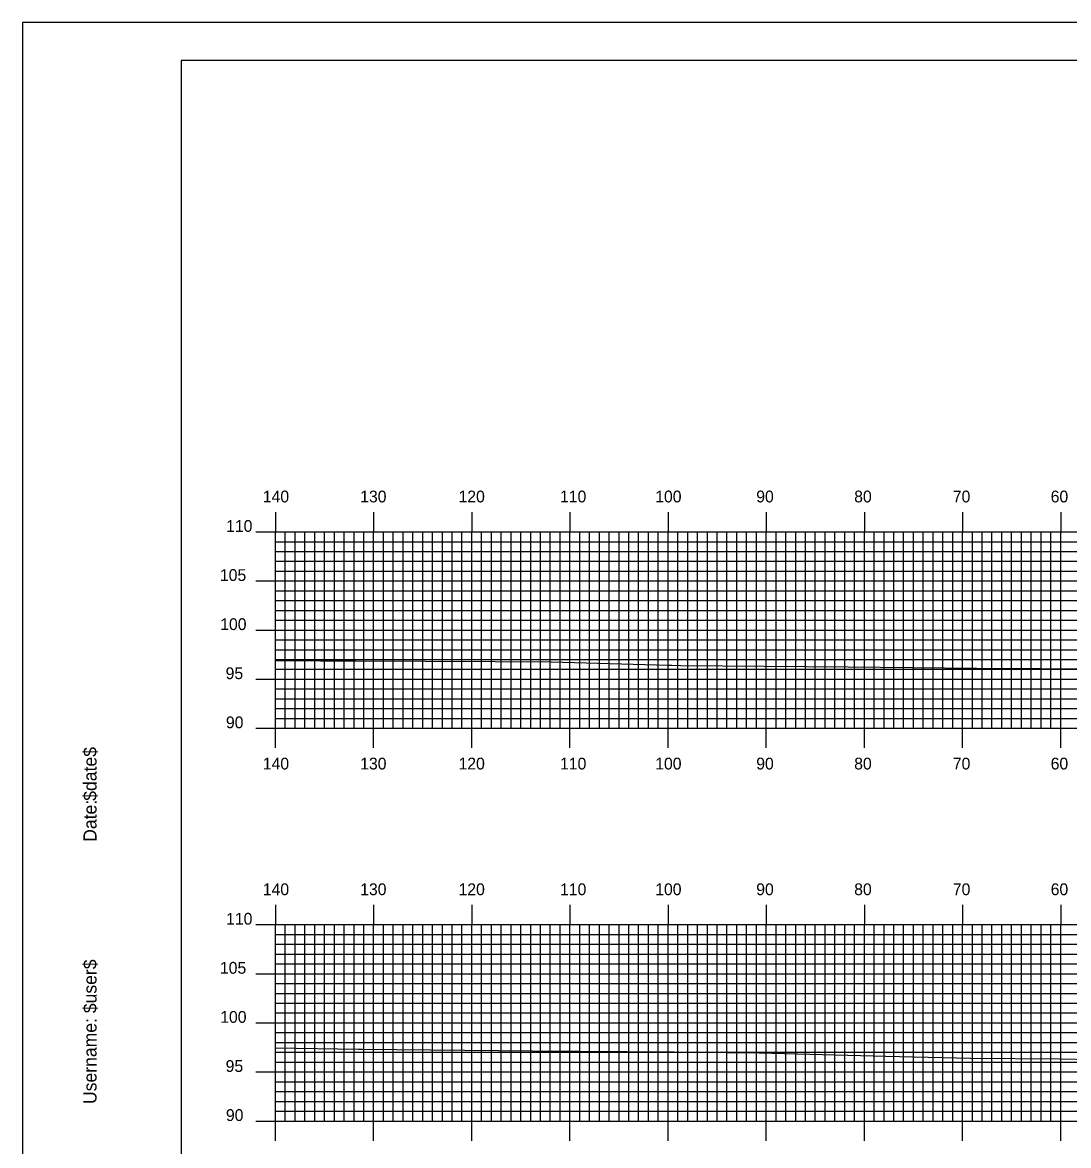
# Model space of a CAD drawing. Extents: x 1764546 to 1764889, y 442591 to 442811.
# Drawn here: x 1764545.6 to 1764652.1, y 442696.2 to 442810.5 of the extents above; entities that cross this region are included whole.
import ezdxf

# ---------------------------------------------------------------- set-up
doc = ezdxf.new("R2010")
doc.units = 0
for name, color, linetype in [('BORDER', 7, 'Continuous'), ('H_V ANNOTATION', 7, 'Continuous'), ('MAJOR', 7, 'Continuous'), ('MINOR', 7, 'Continuous'), ('PLOT BOUNDARY', 7, 'Continuous'), ('S_Roadway_Centerline', 7, 'Continuous')]:
    doc.layers.add(name, color=color, linetype=linetype)

msp = doc.modelspace()

# ---------------------------------------------------------------- linework, layer by layer
at = {"layer": 'BORDER'}
msp.add_lwpolyline([(1764561.74, 442596.67), (1764881.74, 442596.67), (1764881.74, 442806.67), (1764561.74, 442806.67)], close=True, dxfattribs=at)
at = {"layer": 'MAJOR'}
for p, q in [((1764571.34, 442760.67), (1764571.34, 442758.67)), ((1764581.34, 442760.67), (1764581.34, 442758.67)), ((1764591.34, 442760.67), (1764591.34, 442758.67)), ((1764601.34, 442760.67), (1764601.34, 442758.67)), ((1764611.34, 442760.67), (1764611.34, 442758.67)), ((1764621.34, 442760.67), (1764621.34, 442758.67)), ((1764631.34, 442760.67), (1764631.34, 442758.67)), ((1764641.34, 442760.67), (1764641.34, 442758.67)), ((1764651.34, 442760.67), (1764651.34, 442758.67)), ((1764569.34, 442758.67), (1764571.34, 442758.67)), ((1764571.34, 442758.67), (1764851.34, 442758.67)), ((1764571.34, 442738.67), (1764571.34, 442758.67)), ((1764571.34, 442738.67), (1764571.34, 442758.67)), ((1764571.34, 442758.67), (1764851.34, 442758.67)), ((1764581.34, 442738.67), (1764581.34, 442758.67)), ((1764591.34, 442738.67), (1764591.34, 442758.67)), ((1764601.34, 442738.67), (1764601.34, 442758.67)), ((1764611.34, 442738.67), (1764611.34, 442758.67)), ((1764621.34, 442738.67), (1764621.34, 442758.67)), ((1764631.34, 442738.67), (1764631.34, 442758.67)), ((1764641.34, 442738.67), (1764641.34, 442758.67)), ((1764651.34, 442738.67), (1764651.34, 442758.67)), ((1764569.34, 442753.67), (1764571.34, 442753.67)), ((1764571.34, 442753.67), (1764851.34, 442753.67)), ((1764569.34, 442748.67), (1764571.34, 442748.67)), ((1764571.34, 442748.67), (1764851.34, 442748.67)), ((1764569.34, 442743.67), (1764571.34, 442743.67)), ((1764571.34, 442743.67), (1764851.34, 442743.67)), ((1764569.34, 442738.67), (1764571.34, 442738.67)), ((1764571.34, 442738.67), (1764851.34, 442738.67)), ((1764571.34, 442738.67), (1764851.34, 442738.67)), ((1764571.34, 442736.66), (1764571.34, 442738.67)), ((1764581.34, 442736.66), (1764581.34, 442738.67)), ((1764591.34, 442736.66), (1764591.34, 442738.67)), ((1764601.34, 442736.66), (1764601.34, 442738.67)), ((1764611.34, 442736.66), (1764611.34, 442738.67)), ((1764621.34, 442736.66), (1764621.34, 442738.67)), ((1764631.34, 442736.66), (1764631.34, 442738.67)), ((1764641.34, 442736.66), (1764641.34, 442738.67)), ((1764651.34, 442736.66), (1764651.34, 442738.67)), ((1764571.34, 442720.67), (1764571.34, 442718.67)), ((1764581.34, 442720.67), (1764581.34, 442718.67)), ((1764591.34, 442720.67), (1764591.34, 442718.67)), ((1764601.34, 442720.67), (1764601.34, 442718.67)), ((1764611.34, 442720.67), (1764611.34, 442718.67)), ((1764621.34, 442720.67), (1764621.34, 442718.67)), ((1764631.34, 442720.67), (1764631.34, 442718.67)), ((1764641.34, 442720.67), (1764641.34, 442718.67)), ((1764651.34, 442720.67), (1764651.34, 442718.67)), ((1764569.34, 442718.67), (1764571.34, 442718.67)), ((1764571.34, 442718.67), (1764851.34, 442718.67)), ((1764571.34, 442698.67), (1764571.34, 442718.67)), ((1764571.34, 442698.67), (1764571.34, 442718.67)), ((1764571.34, 442718.67), (1764851.34, 442718.67)), ((1764581.34, 442698.67), (1764581.34, 442718.67)), ((1764591.34, 442698.67), (1764591.34, 442718.67)), ((1764601.34, 442698.67), (1764601.34, 442718.67)), ((1764611.34, 442698.67), (1764611.34, 442718.67)), ((1764621.34, 442698.67), (1764621.34, 442718.67)), ((1764631.34, 442698.67), (1764631.34, 442718.67)), ((1764641.34, 442698.67), (1764641.34, 442718.67)), ((1764651.34, 442698.67), (1764651.34, 442718.67)), ((1764569.34, 442713.67), (1764571.34, 442713.67)), ((1764571.34, 442713.67), (1764851.34, 442713.67)), ((1764569.34, 442708.67), (1764571.34, 442708.67)), ((1764571.34, 442708.67), (1764851.34, 442708.67)), ((1764569.34, 442703.67), (1764571.34, 442703.67)), ((1764571.34, 442703.67), (1764851.34, 442703.67)), ((1764569.34, 442698.67), (1764571.34, 442698.67)), ((1764571.34, 442698.67), (1764851.34, 442698.67)), ((1764571.34, 442698.67), (1764851.34, 442698.67)), ((1764571.34, 442696.66), (1764571.34, 442698.67)), ((1764581.34, 442696.66), (1764581.34, 442698.67)), ((1764591.34, 442696.66), (1764591.34, 442698.67)), ((1764601.34, 442696.66), (1764601.34, 442698.67)), ((1764611.34, 442696.66), (1764611.34, 442698.67)), ((1764621.34, 442696.66), (1764621.34, 442698.67)), ((1764631.34, 442696.66), (1764631.34, 442698.67)), ((1764641.34, 442696.66), (1764641.34, 442698.67)), ((1764651.34, 442696.66), (1764651.34, 442698.67))]:
    msp.add_line(p, q, dxfattribs=at)
at = {"layer": 'MINOR'}
for p, q in [((1764572.34, 442738.67), (1764572.34, 442758.67)), ((1764573.34, 442738.67), (1764573.34, 442758.67)), ((1764574.34, 442738.67), (1764574.34, 442758.67)), ((1764575.34, 442738.67), (1764575.34, 442758.67)), ((1764576.34, 442738.67), (1764576.34, 442758.67)), ((1764577.34, 442738.67), (1764577.34, 442758.67)), ((1764578.34, 442738.67), (1764578.34, 442758.67)), ((1764579.34, 442738.67), (1764579.34, 442758.67)), ((1764580.34, 442738.67), (1764580.34, 442758.67)), ((1764582.34, 442738.67), (1764582.34, 442758.67)), ((1764583.34, 442738.67), (1764583.34, 442758.67)), ((1764584.34, 442738.67), (1764584.34, 442758.67)), ((1764585.34, 442738.67), (1764585.34, 442758.67)), ((1764586.34, 442738.67), (1764586.34, 442758.67)), ((1764587.34, 442738.67), (1764587.34, 442758.67)), ((1764588.34, 442738.67), (1764588.34, 442758.67)), ((1764589.34, 442738.67), (1764589.34, 442758.67)), ((1764590.34, 442738.67), (1764590.34, 442758.67)), ((1764592.34, 442738.67), (1764592.34, 442758.67)), ((1764593.34, 442738.67), (1764593.34, 442758.67)), ((1764594.34, 442738.67), (1764594.34, 442758.67)), ((1764595.34, 442738.67), (1764595.34, 442758.67)), ((1764596.34, 442738.67), (1764596.34, 442758.67)), ((1764597.34, 442738.67), (1764597.34, 442758.67)), ((1764598.34, 442738.67), (1764598.34, 442758.67)), ((1764599.34, 442738.67), (1764599.34, 442758.67)), ((1764600.34, 442738.67), (1764600.34, 442758.67)), ((1764602.34, 442738.67), (1764602.34, 442758.67)), ((1764603.34, 442738.67), (1764603.34, 442758.67)), ((1764604.34, 442738.67), (1764604.34, 442758.67)), ((1764605.34, 442738.67), (1764605.34, 442758.67)), ((1764606.34, 442738.67), (1764606.34, 442758.67)), ((1764607.34, 442738.67), (1764607.34, 442758.67)), ((1764608.34, 442738.67), (1764608.34, 442758.67)), ((1764609.34, 442738.67), (1764609.34, 442758.67)), ((1764610.34, 442738.67), (1764610.34, 442758.67)), ((1764612.34, 442738.67), (1764612.34, 442758.67)), ((1764613.34, 442738.67), (1764613.34, 442758.67)), ((1764614.34, 442738.67), (1764614.34, 442758.67)), ((1764615.34, 442738.67), (1764615.34, 442758.67)), ((1764616.34, 442738.67), (1764616.34, 442758.67)), ((1764617.34, 442738.67), (1764617.34, 442758.67)), ((1764618.34, 442738.67), (1764618.34, 442758.67)), ((1764619.34, 442738.67), (1764619.34, 442758.67)), ((1764620.34, 442738.67), (1764620.34, 442758.67)), ((1764622.34, 442738.67), (1764622.34, 442758.67)), ((1764623.34, 442738.67), (1764623.34, 442758.67)), ((1764624.34, 442738.67), (1764624.34, 442758.67)), ((1764625.34, 442738.67), (1764625.34, 442758.67)), ((1764626.34, 442738.67), (1764626.34, 442758.67)), ((1764627.34, 442738.67), (1764627.34, 442758.67)), ((1764628.34, 442738.67), (1764628.34, 442758.67)), ((1764629.34, 442738.67), (1764629.34, 442758.67)), ((1764630.34, 442738.67), (1764630.34, 442758.67)), ((1764632.34, 442738.67), (1764632.34, 442758.67)), ((1764633.34, 442738.67), (1764633.34, 442758.67)), ((1764634.34, 442738.67), (1764634.34, 442758.67)), ((1764635.34, 442738.67), (1764635.34, 442758.67)), ((1764636.34, 442738.67), (1764636.34, 442758.67)), ((1764637.34, 442738.67), (1764637.34, 442758.67)), ((1764638.34, 442738.67), (1764638.34, 442758.67)), ((1764639.34, 442738.67), (1764639.34, 442758.67)), ((1764640.34, 442738.67), (1764640.34, 442758.67)), ((1764642.34, 442738.67), (1764642.34, 442758.67)), ((1764643.34, 442738.67), (1764643.34, 442758.67)), ((1764644.34, 442738.67), (1764644.34, 442758.67)), ((1764645.34, 442738.67), (1764645.34, 442758.67)), ((1764646.34, 442738.67), (1764646.34, 442758.67)), ((1764647.34, 442738.67), (1764647.34, 442758.67)), ((1764648.34, 442738.67), (1764648.34, 442758.67)), ((1764649.34, 442738.67), (1764649.34, 442758.67)), ((1764650.34, 442738.67), (1764650.34, 442758.67)), ((1764571.34, 442757.67), (1764851.34, 442757.67)), ((1764571.34, 442757.67), (1764573.35, 442757.67)), ((1764571.34, 442756.67), (1764851.34, 442756.67)), ((1764571.34, 442756.67), (1764573.35, 442756.67)), ((1764571.34, 442755.67), (1764851.34, 442755.67)), ((1764571.34, 442755.67), (1764573.35, 442755.67)), ((1764571.34, 442754.67), (1764851.34, 442754.67)), ((1764571.34, 442754.67), (1764573.35, 442754.67)), ((1764571.34, 442752.67), (1764851.34, 442752.67)), ((1764571.34, 442752.67), (1764573.35, 442752.67)), ((1764571.34, 442751.67), (1764851.34, 442751.67)), ((1764571.34, 442751.67), (1764573.35, 442751.67)), ((1764571.34, 442750.67), (1764851.34, 442750.67)), ((1764571.34, 442750.67), (1764573.35, 442750.67)), ((1764571.34, 442749.67), (1764851.34, 442749.67)), ((1764571.34, 442749.67), (1764573.35, 442749.67)), ((1764571.34, 442747.67), (1764851.34, 442747.67)), ((1764571.34, 442747.67), (1764573.35, 442747.67)), ((1764571.34, 442746.67), (1764851.34, 442746.67)), ((1764571.34, 442746.67), (1764573.35, 442746.67)), ((1764571.34, 442745.67), (1764851.34, 442745.67)), ((1764571.34, 442745.67), (1764573.35, 442745.67)), ((1764571.34, 442744.67), (1764851.34, 442744.67)), ((1764571.34, 442744.67), (1764573.35, 442744.67)), ((1764571.34, 442742.67), (1764851.34, 442742.67)), ((1764571.34, 442742.67), (1764573.35, 442742.67)), ((1764571.34, 442741.67), (1764851.34, 442741.67)), ((1764571.34, 442741.67), (1764573.35, 442741.67)), ((1764571.34, 442740.67), (1764851.34, 442740.67)), ((1764571.34, 442740.67), (1764573.35, 442740.67)), ((1764571.34, 442739.67), (1764851.34, 442739.67)), ((1764571.34, 442739.67), (1764573.35, 442739.67)), ((1764572.34, 442698.67), (1764572.34, 442718.67)), ((1764573.34, 442698.67), (1764573.34, 442718.67)), ((1764574.34, 442698.67), (1764574.34, 442718.67)), ((1764575.34, 442698.67), (1764575.34, 442718.67)), ((1764576.34, 442698.67), (1764576.34, 442718.67)), ((1764577.34, 442698.67), (1764577.34, 442718.67)), ((1764578.34, 442698.67), (1764578.34, 442718.67)), ((1764579.34, 442698.67), (1764579.34, 442718.67)), ((1764580.34, 442698.67), (1764580.34, 442718.67)), ((1764582.34, 442698.67), (1764582.34, 442718.67)), ((1764583.34, 442698.67), (1764583.34, 442718.67)), ((1764584.34, 442698.67), (1764584.34, 442718.67)), ((1764585.34, 442698.67), (1764585.34, 442718.67)), ((1764586.34, 442698.67), (1764586.34, 442718.67)), ((1764587.34, 442698.67), (1764587.34, 442718.67)), ((1764588.34, 442698.67), (1764588.34, 442718.67)), ((1764589.34, 442698.67), (1764589.34, 442718.67)), ((1764590.34, 442698.67), (1764590.34, 442718.67)), ((1764592.34, 442698.67), (1764592.34, 442718.67)), ((1764593.34, 442698.67), (1764593.34, 442718.67)), ((1764594.34, 442698.67), (1764594.34, 442718.67)), ((1764595.34, 442698.67), (1764595.34, 442718.67)), ((1764596.34, 442698.67), (1764596.34, 442718.67)), ((1764597.34, 442698.67), (1764597.34, 442718.67)), ((1764598.34, 442698.67), (1764598.34, 442718.67)), ((1764599.34, 442698.67), (1764599.34, 442718.67)), ((1764600.34, 442698.67), (1764600.34, 442718.67)), ((1764602.34, 442698.67), (1764602.34, 442718.67)), ((1764603.34, 442698.67), (1764603.34, 442718.67)), ((1764604.34, 442698.67), (1764604.34, 442718.67)), ((1764605.34, 442698.67), (1764605.34, 442718.67)), ((1764606.34, 442698.67), (1764606.34, 442718.67)), ((1764607.34, 442698.67), (1764607.34, 442718.67)), ((1764608.34, 442698.67), (1764608.34, 442718.67)), ((1764609.34, 442698.67), (1764609.34, 442718.67)), ((1764610.34, 442698.67), (1764610.34, 442718.67)), ((1764612.34, 442698.67), (1764612.34, 442718.67)), ((1764613.34, 442698.67), (1764613.34, 442718.67)), ((1764614.34, 442698.67), (1764614.34, 442718.67)), ((1764615.34, 442698.67), (1764615.34, 442718.67)), ((1764616.34, 442698.67), (1764616.34, 442718.67)), ((1764617.34, 442698.67), (1764617.34, 442718.67)), ((1764618.34, 442698.67), (1764618.34, 442718.67)), ((1764619.34, 442698.67), (1764619.34, 442718.67)), ((1764620.34, 442698.67), (1764620.34, 442718.67)), ((1764622.34, 442698.67), (1764622.34, 442718.67)), ((1764623.34, 442698.67), (1764623.34, 442718.67)), ((1764624.34, 442698.67), (1764624.34, 442718.67)), ((1764625.34, 442698.67), (1764625.34, 442718.67)), ((1764626.34, 442698.67), (1764626.34, 442718.67)), ((1764627.34, 442698.67), (1764627.34, 442718.67)), ((1764628.34, 442698.67), (1764628.34, 442718.67)), ((1764629.34, 442698.67), (1764629.34, 442718.67)), ((1764630.34, 442698.67), (1764630.34, 442718.67)), ((1764632.34, 442698.67), (1764632.34, 442718.67)), ((1764633.34, 442698.67), (1764633.34, 442718.67)), ((1764634.34, 442698.67), (1764634.34, 442718.67)), ((1764635.34, 442698.67), (1764635.34, 442718.67)), ((1764636.34, 442698.67), (1764636.34, 442718.67)), ((1764637.34, 442698.67), (1764637.34, 442718.67)), ((1764638.34, 442698.67), (1764638.34, 442718.67)), ((1764639.34, 442698.67), (1764639.34, 442718.67)), ((1764640.34, 442698.67), (1764640.34, 442718.67)), ((1764642.34, 442698.67), (1764642.34, 442718.67)), ((1764643.34, 442698.67), (1764643.34, 442718.67)), ((1764644.34, 442698.67), (1764644.34, 442718.67)), ((1764645.34, 442698.67), (1764645.34, 442718.67)), ((1764646.34, 442698.67), (1764646.34, 442718.67)), ((1764647.34, 442698.67), (1764647.34, 442718.67)), ((1764648.34, 442698.67), (1764648.34, 442718.67)), ((1764649.34, 442698.67), (1764649.34, 442718.67)), ((1764650.34, 442698.67), (1764650.34, 442718.67)), ((1764571.34, 442717.67), (1764851.34, 442717.67)), ((1764571.34, 442717.67), (1764573.35, 442717.67)), ((1764571.34, 442716.67), (1764851.34, 442716.67)), ((1764571.34, 442716.67), (1764573.35, 442716.67)), ((1764571.34, 442715.67), (1764851.34, 442715.67)), ((1764571.34, 442715.67), (1764573.35, 442715.67)), ((1764571.34, 442714.67), (1764851.34, 442714.67)), ((1764571.34, 442714.67), (1764573.35, 442714.67)), ((1764571.34, 442712.67), (1764851.34, 442712.67)), ((1764571.34, 442712.67), (1764573.35, 442712.67)), ((1764571.34, 442711.67), (1764851.34, 442711.67)), ((1764571.34, 442711.67), (1764573.35, 442711.67)), ((1764571.34, 442710.67), (1764851.34, 442710.67)), ((1764571.34, 442710.67), (1764573.35, 442710.67)), ((1764571.34, 442709.67), (1764851.34, 442709.67)), ((1764571.34, 442709.67), (1764573.35, 442709.67)), ((1764571.34, 442707.67), (1764851.34, 442707.67)), ((1764571.34, 442707.67), (1764573.35, 442707.67)), ((1764571.34, 442706.67), (1764851.34, 442706.67)), ((1764571.34, 442706.67), (1764573.35, 442706.67)), ((1764571.34, 442705.67), (1764851.34, 442705.67)), ((1764571.34, 442705.67), (1764573.35, 442705.67)), ((1764571.34, 442704.67), (1764851.34, 442704.67)), ((1764571.34, 442704.67), (1764573.35, 442704.67)), ((1764571.34, 442702.67), (1764851.34, 442702.67)), ((1764571.34, 442702.67), (1764573.35, 442702.67)), ((1764571.34, 442701.67), (1764851.34, 442701.67)), ((1764571.34, 442701.67), (1764573.35, 442701.67)), ((1764571.34, 442700.67), (1764851.34, 442700.67)), ((1764571.34, 442700.67), (1764573.35, 442700.67)), ((1764571.34, 442699.67), (1764851.34, 442699.67)), ((1764571.34, 442699.67), (1764573.35, 442699.67))]:
    msp.add_line(p, q, dxfattribs=at)
at = {"layer": 'PLOT BOUNDARY'}
msp.add_lwpolyline([(1764545.56, 442590.55), (1764885.56, 442590.55), (1764885.56, 442810.55), (1764545.56, 442810.55)], close=True, dxfattribs=at)
at = {"layer": 'S_Roadway_Centerline'}
for points in [[(1764571.34, 442745.57), (1764575.91, 442745.53), (1764579.48, 442745.52), (1764593.72, 442745.47), (1764599.44, 442745.43), (1764611.34, 442745.08), (1764611.73, 442745.08), (1764612.61, 442745.07), (1764629.67, 442744.92), (1764642.8, 442744.78), (1764647.44, 442744.75), (1764649.26, 442744.75), (1764653.5, 442744.73)], [(1764571.34, 442706.11), (1764579.79, 442705.98), (1764580.21, 442705.98), (1764597.52, 442705.83), (1764611.95, 442705.71), (1764615.81, 442705.67), (1764617.26, 442705.66), (1764620.62, 442705.61), (1764633.52, 442705.29), (1764642.15, 442705.08), (1764651.22, 442705.01), (1764661.44, 442704.81)]]:
    msp.add_lwpolyline(points, dxfattribs=at)

# ---------------------------------------------------------------- texts
at = {"layer": 'BORDER'}
for s, p in [('$date$', (1764553.11, 442731.28)), ('Date:', (1764553.11, 442727.1)), ('$user$', (1764553.11, 442709.65)), ('Username:', (1764553.11, 442700.4))]:
    msp.add_text(s, height=1.339, rotation=90, dxfattribs=at).set_placement(p)
at = {"layer": 'H_V ANNOTATION'}
for s, p in [('140', (1764570.05, 442761.67)), ('130', (1764579.97, 442761.67)), ('120', (1764589.99, 442761.67)), ('110', (1764600.33, 442761.67)), ('100', (1764610.03, 442761.67)), ('90', (1764620.32, 442761.67)), ('80', (1764630.3, 442761.67)), ('70', (1764640.35, 442761.67)), ('60', (1764650.32, 442761.67)), ('110', (1764566.31, 442758.67)), ('105', (1764565.68, 442753.67)), ('100', (1764565.71, 442748.67)), ('95', (1764566.26, 442743.67)), ('90', (1764566.29, 442738.67)), ('140', (1764570.05, 442734.47)), ('130', (1764579.97, 442734.47)), ('120', (1764589.99, 442734.47)), ('110', (1764600.33, 442734.47)), ('100', (1764610.03, 442734.47)), ('90', (1764620.32, 442734.47)), ('80', (1764630.3, 442734.47)), ('70', (1764640.35, 442734.47)), ('60', (1764650.32, 442734.47)), ('140', (1764570.05, 442721.67)), ('130', (1764579.97, 442721.67)), ('120', (1764589.99, 442721.67)), ('110', (1764600.33, 442721.67)), ('100', (1764610.03, 442721.67)), ('90', (1764620.32, 442721.67)), ('80', (1764630.3, 442721.67)), ('70', (1764640.35, 442721.67)), ('60', (1764650.32, 442721.67)), ('110', (1764566.31, 442718.67)), ('105', (1764565.68, 442713.67)), ('100', (1764565.71, 442708.67)), ('95', (1764566.26, 442703.67)), ('90', (1764566.29, 442698.67))]:
    msp.add_text(s, height=1.2, dxfattribs=at).set_placement(p)
at = {"layer": 'MAJOR'}
for p in [(1764571.34, 442738.67), (1764571.34, 442698.67)]:
    msp.add_text('-', height=0.012, dxfattribs=at).set_placement(p)

doc.saveas('drawing.dxf')
